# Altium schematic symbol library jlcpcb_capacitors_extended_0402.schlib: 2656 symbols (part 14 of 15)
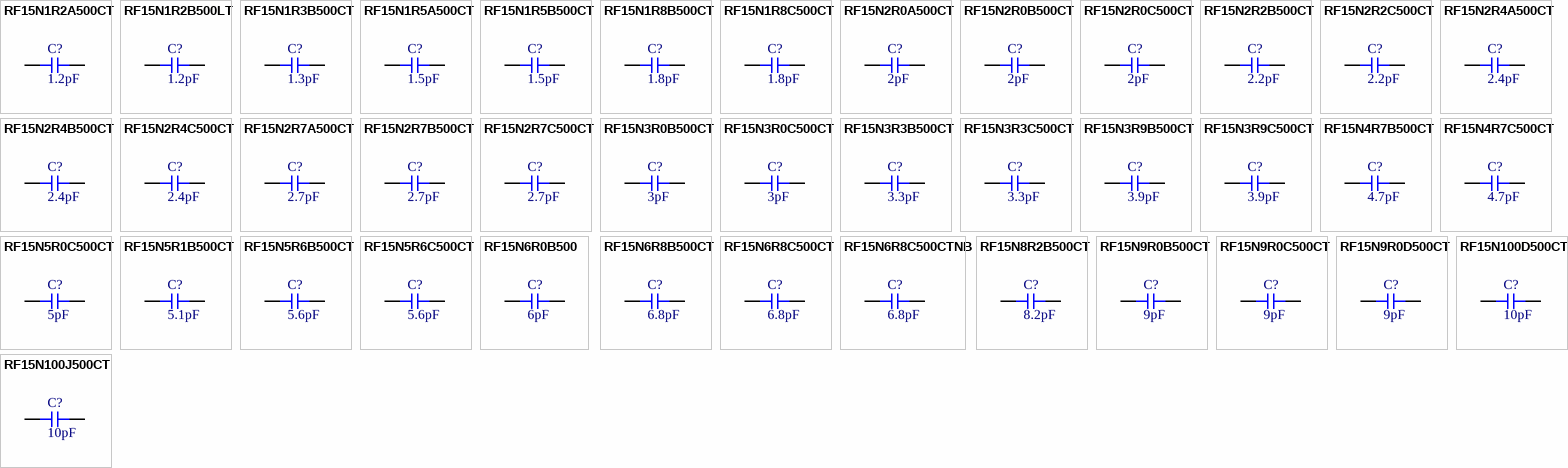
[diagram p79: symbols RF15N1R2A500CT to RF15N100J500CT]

## RF15N2R0B500CT
designator C?  Capacitance: 2pF  (hidden comment: *)
Capacitor, Ceramic (MLCC), 2pF, ±0.1pF, 50V, NP0, ±0.1pF, SMD 0402; Manufacturer: Walsin Tech Corp; Manufacturer Part Number: RF15N2R0B500CT
footprint CAP-0402 (0402 (1005M) Capacitor)
pins: 1, 2

## RF15N2R0C500CT
designator C?  Capacitance: 2pF  (hidden comment: *)
Capacitor, Ceramic (MLCC), 2pF, ±0.25pF, 50V, NP0, ±0.25pF, SMD 0402; Manufacturer: Walsin Tech Corp; Manufacturer Part Number: RF15N2R0C500CT
footprint CAP-0402 (0402 (1005M) Capacitor)
pins: 1, 2

## RF15N2R2B500CT
designator C?  Capacitance: 2.2pF  (hidden comment: *)
Capacitor, Ceramic (MLCC), 2.2pF, ±0.1pF, 50V, NP0, ±0.1pF, SMD 0402; Manufacturer: Walsin Tech Corp; Manufacturer Part Number: RF15N2R2B500CT
footprint CAP-0402 (0402 (1005M) Capacitor)
pins: 1, 2

## RF15N2R2C500CT
designator C?  Capacitance: 2.2pF  (hidden comment: *)
Capacitor, Ceramic (MLCC), 2.2pF, ±0.25pF, 50V, NP0, ±0.25pF, SMD 0402; Manufacturer: Walsin Tech Corp; Manufacturer Part Number: RF15N2R2C500CT
footprint CAP-0402 (0402 (1005M) Capacitor)
pins: 1, 2

## RF15N2R4A500CT
designator C?  Capacitance: 2.4pF  (hidden comment: *)
Capacitor, Ceramic (MLCC), 2.4pF, ±0.05pF, 50V, NP0, ±0.05pF, SMD 0402; Manufacturer: Walsin Tech Corp; Manufacturer Part Number: RF15N2R4A500CT
footprint CAP-0402 (0402 (1005M) Capacitor)
pins: 1, 2

## RF15N2R4B500CT
designator C?  Capacitance: 2.4pF  (hidden comment: *)
Capacitor, Ceramic (MLCC), 2.4pF, ±0.1pF, 50V, NP0, ±0.1pF, SMD 0402; Manufacturer: Walsin Tech Corp; Manufacturer Part Number: RF15N2R4B500CT
footprint CAP-0402 (0402 (1005M) Capacitor)
pins: 1, 2

## RF15N2R4C500CT
designator C?  Capacitance: 2.4pF  (hidden comment: *)
Capacitor, Ceramic (MLCC), 2.4pF, ±0.25pF, 50V, NP0, ±0.25pF, SMD 0402; Manufacturer: Walsin Tech Corp; Manufacturer Part Number: RF15N2R4C500CT
footprint CAP-0402 (0402 (1005M) Capacitor)
pins: 1, 2

## RF15N2R7A500CT
designator C?  Capacitance: 2.7pF  (hidden comment: *)
Capacitor, Ceramic (MLCC), 2.7pF, ±0.05pF, 50V, NP0, ±0.05pF, SMD 0402; Manufacturer: Walsin Tech Corp; Manufacturer Part Number: RF15N2R7A500CT
footprint CAP-0402 (0402 (1005M) Capacitor)
pins: 1, 2

## RF15N2R7B500CT
designator C?  Capacitance: 2.7pF  (hidden comment: *)
Capacitor, Ceramic (MLCC), 2.7pF, ±0.1pF, 50V, NP0, ±0.1pF, SMD 0402; Manufacturer: Walsin Tech Corp; Manufacturer Part Number: RF15N2R7B500CT
footprint CAP-0402 (0402 (1005M) Capacitor)
pins: 1, 2

## RF15N2R7C500CT
designator C?  Capacitance: 2.7pF  (hidden comment: *)
Capacitor, Ceramic (MLCC), 2.7pF, ±0.25pF, 50V, NP0, ±0.25pF, SMD 0402; Manufacturer: Walsin Tech Corp; Manufacturer Part Number: RF15N2R7C500CT
footprint CAP-0402 (0402 (1005M) Capacitor)
pins: 1, 2

## RF15N3R0B500CT
designator C?  Capacitance: 3pF  (hidden comment: *)
Capacitor, Ceramic (MLCC), 3pF, ±0.1pF, 50V, NP0, ±0.1pF, SMD 0402; Manufacturer: Walsin Tech Corp; Manufacturer Part Number: RF15N3R0B500CT
footprint CAP-0402 (0402 (1005M) Capacitor)
pins: 1, 2

## RF15N3R0C500CT
designator C?  Capacitance: 3pF  (hidden comment: *)
Capacitor, Ceramic (MLCC), 3pF, ±0.25pF, 50V, NP0, ±0.25pF, SMD 0402; Manufacturer: Walsin Tech Corp; Manufacturer Part Number: RF15N3R0C500CT
footprint CAP-0402 (0402 (1005M) Capacitor)
pins: 1, 2

## RF15N3R3B500CT
designator C?  Capacitance: 3.3pF  (hidden comment: *)
Capacitor, Ceramic (MLCC), 3.3pF, ±0.1pF, 50V, NP0, ±0.1pF, SMD 0402; Manufacturer: Walsin Tech Corp; Manufacturer Part Number: RF15N3R3B500CT
footprint CAP-0402 (0402 (1005M) Capacitor)
pins: 1, 2

## RF15N3R3C500CT
designator C?  Capacitance: 3.3pF  (hidden comment: *)
Capacitor, Ceramic (MLCC), 3.3pF, ±0.25pF, 50V, NP0, ±0.25pF, SMD 0402; Manufacturer: Walsin Tech Corp; Manufacturer Part Number: RF15N3R3C500CT
footprint CAP-0402 (0402 (1005M) Capacitor)
pins: 1, 2

## RF15N3R9B500CT
designator C?  Capacitance: 3.9pF  (hidden comment: *)
Capacitor, Ceramic (MLCC), 3.9pF, ±0.1pF, 50V, NP0, ±0.1pF, SMD 0402; Manufacturer: Walsin Tech Corp; Manufacturer Part Number: RF15N3R9B500CT
footprint CAP-0402 (0402 (1005M) Capacitor)
pins: 1, 2

## RF15N3R9C500CT
designator C?  Capacitance: 3.9pF  (hidden comment: *)
Capacitor, Ceramic (MLCC), 3.9pF, ±0.25pF, 50V, NP0, ±0.25pF, SMD 0402; Manufacturer: Walsin Tech Corp; Manufacturer Part Number: RF15N3R9C500CT
footprint CAP-0402 (0402 (1005M) Capacitor)
pins: 1, 2

## RF15N4R7B500CT
designator C?  Capacitance: 4.7pF  (hidden comment: *)
Capacitor, Ceramic (MLCC), 4.7pF, ±0.1pF, 50V, NP0, ±0.1pF, SMD 0402; Manufacturer: Walsin Tech Corp; Manufacturer Part Number: RF15N4R7B500CT
footprint CAP-0402 (0402 (1005M) Capacitor)
pins: 1, 2

## RF15N4R7C500CT
designator C?  Capacitance: 4.7pF  (hidden comment: *)
Capacitor, Ceramic (MLCC), 4.7pF, ±0.25pF, 50V, NP0, ±0.25pF, SMD 0402; Manufacturer: Walsin Tech Corp; Manufacturer Part Number: RF15N4R7C500CT
footprint CAP-0402 (0402 (1005M) Capacitor)
pins: 1, 2

## RF15N5R0C500CT
designator C?  Capacitance: 5pF  (hidden comment: *)
Capacitor, Ceramic (MLCC), 5pF, ±0.25pF, 50V, NP0, ±0.25pF, SMD 0402; Manufacturer: Walsin Tech Corp; Manufacturer Part Number: RF15N5R0C500CT
footprint CAP-0402 (0402 (1005M) Capacitor)
pins: 1, 2

## RF15N5R1B500CT
designator C?  Capacitance: 5.1pF  (hidden comment: *)
Capacitor, Ceramic (MLCC), 5.1pF, ±0.1pF, 50V, NP0, ±0.1pF, SMD 0402; Manufacturer: Walsin Tech Corp; Manufacturer Part Number: RF15N5R1B500CT
footprint CAP-0402 (0402 (1005M) Capacitor)
pins: 1, 2

## RF15N5R6B500CT
designator C?  Capacitance: 5.6pF  (hidden comment: *)
Capacitor, Ceramic (MLCC), 5.6pF, ±0.1pF, 50V, NP0, ±0.1pF, SMD 0402; Manufacturer: Walsin Tech Corp; Manufacturer Part Number: RF15N5R6B500CT
footprint CAP-0402 (0402 (1005M) Capacitor)
pins: 1, 2

## RF15N5R6C500CT
designator C?  Capacitance: 5.6pF  (hidden comment: *)
Capacitor, Ceramic (MLCC), 5.6pF, ±0.25pF, 50V, NP0, ±0.25pF, SMD 0402; Manufacturer: Walsin Tech Corp; Manufacturer Part Number: RF15N5R6C500CT
footprint CAP-0402 (0402 (1005M) Capacitor)
pins: 1, 2

## RF15N6R0B500
designator C?  Capacitance: 6pF  (hidden comment: *)
Capacitor, Ceramic (MLCC), 6pF, ±0.1pF, 50V, NP0, ±0.1pF, SMD 0402; Manufacturer: Walsin Tech Corp; Manufacturer Part Number: RF15N6R0B500
footprint CAP-0402 (0402 (1005M) Capacitor)
pins: 1, 2

## RF15N6R8B500CT
designator C?  Capacitance: 6.8pF  (hidden comment: *)
Capacitor, Ceramic (MLCC), 6.8pF, ±0.1pF, 50V, NP0, ±0.1pF, SMD 0402; Manufacturer: Walsin Tech Corp; Manufacturer Part Number: RF15N6R8B500CT
footprint CAP-0402 (0402 (1005M) Capacitor)
pins: 1, 2

## RF15N6R8C500CT
designator C?  Capacitance: 6.8pF  (hidden comment: *)
Capacitor, Ceramic (MLCC), 6.8pF, ±0.25pF, 50V, NP0, ±0.25pF, SMD 0402; Manufacturer: Walsin Tech Corp; Manufacturer Part Number: RF15N6R8C500CT
footprint CAP-0402 (0402 (1005M) Capacitor)
pins: 1, 2

## RF15N6R8C500CTNB
designator C?  Capacitance: 6.8pF  (hidden comment: *)
Capacitor, Ceramic (MLCC), 6.8pF, ±0.25pF, 50V, NP0, ±0.25pF, SMD 0402; Manufacturer: Walsin Tech Corp; Manufacturer Part Number: RF15N6R8C500CTNB
footprint CAP-0402 (0402 (1005M) Capacitor)
pins: 1, 2

## RF15N8R2B500CT
designator C?  Capacitance: 8.2pF  (hidden comment: *)
Capacitor, Ceramic (MLCC), 8.2pF, ±0.1pF, 50V, NP0, ±0.1pF, SMD 0402; Manufacturer: Walsin Tech Corp; Manufacturer Part Number: RF15N8R2B500CT
footprint CAP-0402 (0402 (1005M) Capacitor)
pins: 1, 2

## RF15N9R0B500CT
designator C?  Capacitance: 9pF  (hidden comment: *)
Capacitor, Ceramic (MLCC), 9pF, ±0.1pF, 50V, NP0, ±0.1pF, SMD 0402; Manufacturer: Walsin Tech Corp; Manufacturer Part Number: RF15N9R0B500CT
footprint CAP-0402 (0402 (1005M) Capacitor)
pins: 1, 2

## RF15N9R0C500CT
designator C?  Capacitance: 9pF  (hidden comment: *)
Capacitor, Ceramic (MLCC), 9pF, ±0.25pF, 50V, NP0, ±0.25pF, SMD 0402; Manufacturer: Walsin Tech Corp; Manufacturer Part Number: RF15N9R0C500CT
footprint CAP-0402 (0402 (1005M) Capacitor)
pins: 1, 2

## RF15N9R0D500CT
designator C?  Capacitance: 9pF  (hidden comment: *)
Capacitor, Ceramic (MLCC), 9pF, ±0.5pF, 50V, NP0, ±0.5pF, SMD 0402; Manufacturer: Walsin Tech Corp; Manufacturer Part Number: RF15N9R0D500CT
footprint CAP-0402 (0402 (1005M) Capacitor)
pins: 1, 2

## RF15N100D500CT
designator C?  Capacitance: 10pF  (hidden comment: *)
Capacitor, Ceramic (MLCC), 10pF, ±0.5pF, 50V, NP0, ±0.5pF, SMD 0402; Manufacturer: Walsin Tech Corp; Manufacturer Part Number: RF15N100D500CT
footprint CAP-0402 (0402 (1005M) Capacitor)
pins: 1, 2

## RF15N100J500CT
designator C?  Capacitance: 10pF  (hidden comment: *)
Capacitor, Ceramic (MLCC), 10pF, ±5%, 50V, NP0, ±5%, SMD 0402; Manufacturer: Walsin Tech Corp; Manufacturer Part Number: RF15N100J500CT
footprint CAP-0402 (0402 (1005M) Capacitor)
pins: 1, 2

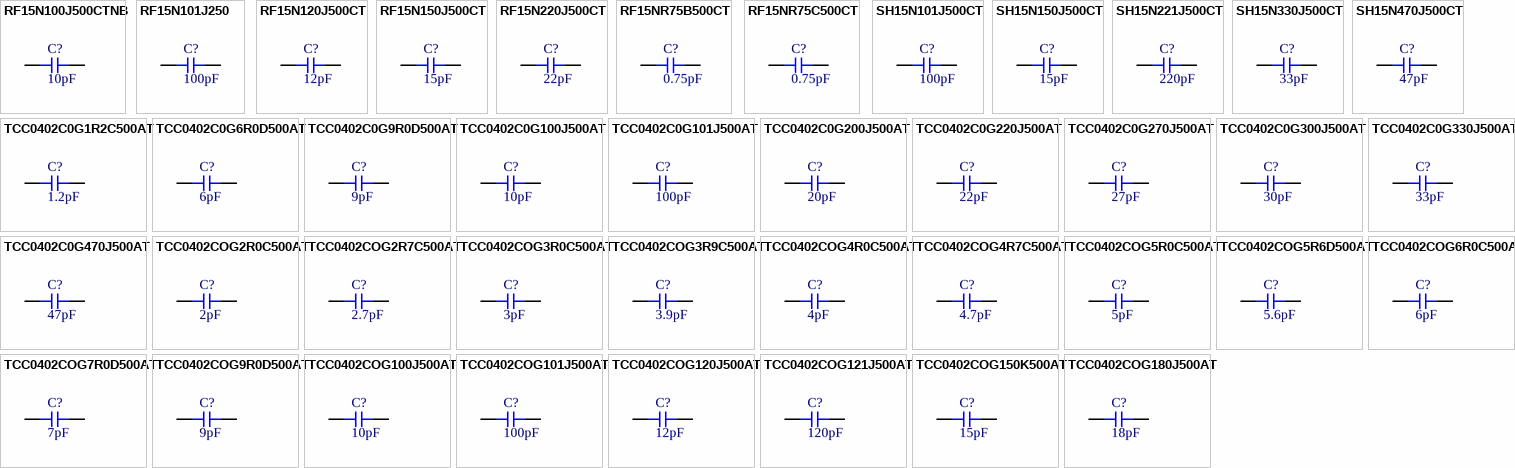
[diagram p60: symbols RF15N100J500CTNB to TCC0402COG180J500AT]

## RF15N100J500CTNB
designator C?  Capacitance: 10pF  (hidden comment: *)
Capacitor, Ceramic (MLCC), 10pF, ±5%, 50V, NP0, ±5%, SMD 0402; Manufacturer: Walsin Tech Corp; Manufacturer Part Number: RF15N100J500CTNB
footprint CAP-0402 (0402 (1005M) Capacitor)
pins: 1, 2

## RF15N101J250
designator C?  Capacitance: 100pF  (hidden comment: *)
Capacitor, Ceramic (MLCC), 100pF, ±5%, 25V, NP0, ±5%, SMD 0402; Manufacturer: Walsin Tech Corp; Manufacturer Part Number: RF15N101J250
footprint CAP-0402 (0402 (1005M) Capacitor)
pins: 1, 2

## RF15N120J500CT
designator C?  Capacitance: 12pF  (hidden comment: *)
Capacitor, Ceramic (MLCC), 12pF, ±5%, 50V, NP0, ±5%, SMD 0402; Manufacturer: Walsin Tech Corp; Manufacturer Part Number: RF15N120J500CT
footprint CAP-0402 (0402 (1005M) Capacitor)
pins: 1, 2

## RF15N150J500CT
designator C?  Capacitance: 15pF  (hidden comment: *)
Capacitor, Ceramic (MLCC), 15pF, ±5%, 50V, NP0, ±5%, SMD 0402; Manufacturer: Walsin Tech Corp; Manufacturer Part Number: RF15N150J500CT
footprint CAP-0402 (0402 (1005M) Capacitor)
pins: 1, 2

## RF15N220J500CT
designator C?  Capacitance: 22pF  (hidden comment: *)
Capacitor, Ceramic (MLCC), 22pF, ±5%, 50V, NP0, ±5%, SMD 0402; Manufacturer: Walsin Tech Corp; Manufacturer Part Number: RF15N220J500CT
footprint CAP-0402 (0402 (1005M) Capacitor)
pins: 1, 2

## RF15NR75B500CT
designator C?  Capacitance: 0.75pF  (hidden comment: *)
Capacitor, Ceramic (MLCC), 0.75pF, ±0.1pF, 50V, NP0, ±0.1pF, SMD 0402; Manufacturer: Walsin Tech Corp; Manufacturer Part Number: RF15NR75B500CT
footprint CAP-0402 (0402 (1005M) Capacitor)
pins: 1, 2

## RF15NR75C500CT
designator C?  Capacitance: 0.75pF  (hidden comment: *)
Capacitor, Ceramic (MLCC), 0.75pF, ±0.25pF, 50V, NP0, ±0.25pF, SMD 0402; Manufacturer: Walsin Tech Corp; Manufacturer Part Number: RF15NR75C500CT
footprint CAP-0402 (0402 (1005M) Capacitor)
pins: 1, 2

## SH15N101J500CT
designator C?  Capacitance: 100pF  (hidden comment: *)
Capacitor, Ceramic (MLCC), 100pF, ±5%, 50V, NP0, ±5%, SMD 0402; Manufacturer: Walsin Tech Corp; Manufacturer Part Number: SH15N101J500CT
footprint CAP-0402 (0402 (1005M) Capacitor)
pins: 1, 2

## SH15N150J500CT
designator C?  Capacitance: 15pF  (hidden comment: *)
Capacitor, Ceramic (MLCC), 15pF, ±5%, 50V, NP0, ±5%, SMD 0402; Manufacturer: Walsin Tech Corp; Manufacturer Part Number: SH15N150J500CT
footprint CAP-0402 (0402 (1005M) Capacitor)
pins: 1, 2

## SH15N221J500CT
designator C?  Capacitance: 220pF  (hidden comment: *)
Capacitor, Ceramic (MLCC), 220pF, ±5%, 50V, NP0, ±5%, SMD 0402; Manufacturer: Walsin Tech Corp; Manufacturer Part Number: SH15N221J500CT
footprint CAP-0402 (0402 (1005M) Capacitor)
pins: 1, 2

## SH15N330J500CT
designator C?  Capacitance: 33pF  (hidden comment: *)
Capacitor, Ceramic (MLCC), 33pF, ±5%, 50V, NP0, ±5%, SMD 0402; Manufacturer: Walsin Tech Corp; Manufacturer Part Number: SH15N330J500CT
footprint CAP-0402 (0402 (1005M) Capacitor)
pins: 1, 2

## SH15N470J500CT
designator C?  Capacitance: 47pF  (hidden comment: *)
Capacitor, Ceramic (MLCC), 47pF, ±5%, 50V, NP0, ±5%, SMD 0402; Manufacturer: Walsin Tech Corp; Manufacturer Part Number: SH15N470J500CT
footprint CAP-0402 (0402 (1005M) Capacitor)
pins: 1, 2

## TCC0402C0G1R2C500AT
designator C?  Capacitance: 1.2pF  (hidden comment: *)
Capacitor, Ceramic (MLCC), 1.2pF, ±0.25pF, 50V, C0G, ±0.25pF, SMD 0402; Manufacturer: CCTC; Manufacturer Part Number: TCC0402C0G1R2C500AT
footprint CAP-0402 (0402 (1005M) Capacitor)
pins: 1, 2

## TCC0402C0G6R0D500AT
designator C?  Capacitance: 6pF  (hidden comment: *)
Capacitor, Ceramic (MLCC), 6pF, ±0.5pF, 50V, C0G, ±0.5pF, SMD 0402; Manufacturer: CCTC; Manufacturer Part Number: TCC0402C0G6R0D500AT
footprint CAP-0402 (0402 (1005M) Capacitor)
pins: 1, 2

## TCC0402C0G9R0D500AT
designator C?  Capacitance: 9pF  (hidden comment: *)
Capacitor, Ceramic (MLCC), 9pF, ±0.5pF, 50V, C0G, ±0.5pF, SMD 0402; Manufacturer: CCTC; Manufacturer Part Number: TCC0402C0G9R0D500AT
footprint CAP-0402 (0402 (1005M) Capacitor)
pins: 1, 2

## TCC0402C0G100J500AT
designator C?  Capacitance: 10pF  (hidden comment: *)
Capacitor, Ceramic (MLCC), 10pF, ±5%, 50V, C0G, ±5%, SMD 0402; Manufacturer: CCTC; Manufacturer Part Number: TCC0402C0G100J500AT
footprint CAP-0402 (0402 (1005M) Capacitor)
pins: 1, 2

## TCC0402C0G101J500AT
designator C?  Capacitance: 100pF  (hidden comment: *)
Capacitor, Ceramic (MLCC), 100pF, ±5%, 50V, C0G, ±5%, SMD 0402; Manufacturer: CCTC; Manufacturer Part Number: TCC0402C0G101J500AT
footprint CAP-0402 (0402 (1005M) Capacitor)
pins: 1, 2

## TCC0402C0G200J500AT
designator C?  Capacitance: 20pF  (hidden comment: *)
Capacitor, Ceramic (MLCC), 20pF, ±5%, 50V, C0G, ±5%, SMD 0402; Manufacturer: CCTC; Manufacturer Part Number: TCC0402C0G200J500AT
footprint CAP-0402 (0402 (1005M) Capacitor)
pins: 1, 2

## TCC0402C0G220J500AT
designator C?  Capacitance: 22pF  (hidden comment: *)
Capacitor, Ceramic (MLCC), 22pF, ±5%, 50V, C0G, ±5%, SMD 0402; Manufacturer: CCTC; Manufacturer Part Number: TCC0402C0G220J500AT
footprint CAP-0402 (0402 (1005M) Capacitor)
pins: 1, 2

## TCC0402C0G270J500AT
designator C?  Capacitance: 27pF  (hidden comment: *)
Capacitor, Ceramic (MLCC), 27pF, ±5%, 50V, C0G, ±5%, SMD 0402; Manufacturer: CCTC; Manufacturer Part Number: TCC0402C0G270J500AT
footprint CAP-0402 (0402 (1005M) Capacitor)
pins: 1, 2

## TCC0402C0G300J500AT
designator C?  Capacitance: 30pF  (hidden comment: *)
Capacitor, Ceramic (MLCC), 30pF, ±5%, 50V, C0G, ±5%, SMD 0402; Manufacturer: CCTC; Manufacturer Part Number: TCC0402C0G300J500AT
footprint CAP-0402 (0402 (1005M) Capacitor)
pins: 1, 2

## TCC0402C0G330J500AT
designator C?  Capacitance: 33pF  (hidden comment: *)
Capacitor, Ceramic (MLCC), 33pF, ±5%, 50V, C0G, ±5%, SMD 0402; Manufacturer: CCTC; Manufacturer Part Number: TCC0402C0G330J500AT
footprint CAP-0402 (0402 (1005M) Capacitor)
pins: 1, 2

## TCC0402C0G470J500AT
designator C?  Capacitance: 47pF  (hidden comment: *)
Capacitor, Ceramic (MLCC), 47pF, ±5%, 50V, C0G, ±5%, SMD 0402; Manufacturer: CCTC; Manufacturer Part Number: TCC0402C0G470J500AT
footprint CAP-0402 (0402 (1005M) Capacitor)
pins: 1, 2

## TCC0402COG2R0C500AT
designator C?  Capacitance: 2pF  (hidden comment: *)
Capacitor, Ceramic (MLCC), 2pF, ±0.25pF, 50V, C0G, ±0.25pF, SMD 0402; Manufacturer: CCTC; Manufacturer Part Number: TCC0402COG2R0C500AT
footprint CAP-0402 (0402 (1005M) Capacitor)
pins: 1, 2

## TCC0402COG2R7C500AT
designator C?  Capacitance: 2.7pF  (hidden comment: *)
Capacitor, Ceramic (MLCC), 2.7pF, ±0.25pF, 50V, C0G, ±0.25pF, SMD 0402; Manufacturer: CCTC; Manufacturer Part Number: TCC0402COG2R7C500AT
footprint CAP-0402 (0402 (1005M) Capacitor)
pins: 1, 2

## TCC0402COG3R0C500AT
designator C?  Capacitance: 3pF  (hidden comment: *)
Capacitor, Ceramic (MLCC), 3pF, ±0.25pF, 50V, C0G, ±0.25pF, SMD 0402; Manufacturer: CCTC; Manufacturer Part Number: TCC0402COG3R0C500AT
footprint CAP-0402 (0402 (1005M) Capacitor)
pins: 1, 2

## TCC0402COG3R9C500AT
designator C?  Capacitance: 3.9pF  (hidden comment: *)
Capacitor, Ceramic (MLCC), 3.9pF, ±0.25pF, 50V, C0G, ±0.25pF, SMD 0402; Manufacturer: CCTC; Manufacturer Part Number: TCC0402COG3R9C500AT
footprint CAP-0402 (0402 (1005M) Capacitor)
pins: 1, 2

## TCC0402COG4R0C500AT
designator C?  Capacitance: 4pF  (hidden comment: *)
Capacitor, Ceramic (MLCC), 4pF, ±0.25pF, 50V, C0G, ±0.25pF, SMD 0402; Manufacturer: CCTC; Manufacturer Part Number: TCC0402COG4R0C500AT
footprint CAP-0402 (0402 (1005M) Capacitor)
pins: 1, 2

## TCC0402COG4R7C500AT
designator C?  Capacitance: 4.7pF  (hidden comment: *)
Capacitor, Ceramic (MLCC), 4.7pF, ±0.25pF, 50V, C0G, ±0.25pF, SMD 0402; Manufacturer: CCTC; Manufacturer Part Number: TCC0402COG4R7C500AT
footprint CAP-0402 (0402 (1005M) Capacitor)
pins: 1, 2

## TCC0402COG5R0C500AT
designator C?  Capacitance: 5pF  (hidden comment: *)
Capacitor, Ceramic (MLCC), 5pF, ±0.25pF, 50V, C0G, ±0.25pF, SMD 0402; Manufacturer: CCTC; Manufacturer Part Number: TCC0402COG5R0C500AT
footprint CAP-0402 (0402 (1005M) Capacitor)
pins: 1, 2

## TCC0402COG5R6D500AT
designator C?  Capacitance: 5.6pF  (hidden comment: *)
Capacitor, Ceramic (MLCC), 5.6pF, ±0.5pF, 50V, C0G, ±0.5pF, SMD 0402; Manufacturer: CCTC; Manufacturer Part Number: TCC0402COG5R6D500AT
footprint CAP-0402 (0402 (1005M) Capacitor)
pins: 1, 2

## TCC0402COG6R0C500AT
designator C?  Capacitance: 6pF  (hidden comment: *)
Capacitor, Ceramic (MLCC), 6pF, ±0.25pF, 50V, C0G, ±0.25pF, SMD 0402; Manufacturer: CCTC; Manufacturer Part Number: TCC0402COG6R0C500AT
footprint CAP-0402 (0402 (1005M) Capacitor)
pins: 1, 2

## TCC0402COG7R0D500AT
designator C?  Capacitance: 7pF  (hidden comment: *)
Capacitor, Ceramic (MLCC), 7pF, ±0.5pF, 50V, C0G, ±0.5pF, SMD 0402; Manufacturer: CCTC; Manufacturer Part Number: TCC0402COG7R0D500AT
footprint CAP-0402 (0402 (1005M) Capacitor)
pins: 1, 2

## TCC0402COG9R0D500AT
designator C?  Capacitance: 9pF  (hidden comment: *)
Capacitor, Ceramic (MLCC), 9pF, ±0.5pF, 50V, C0G, ±0.5pF, SMD 0402; Manufacturer: CCTC; Manufacturer Part Number: TCC0402COG9R0D500AT
footprint CAP-0402 (0402 (1005M) Capacitor)
pins: 1, 2

## TCC0402COG100J500AT
designator C?  Capacitance: 10pF  (hidden comment: *)
Capacitor, Ceramic (MLCC), 10pF, ±5%, 50V, C0G, ±5%, SMD 0402; Manufacturer: CCTC; Manufacturer Part Number: TCC0402COG100J500AT
footprint CAP-0402 (0402 (1005M) Capacitor)
pins: 1, 2

## TCC0402COG101J500AT
designator C?  Capacitance: 100pF  (hidden comment: *)
Capacitor, Ceramic (MLCC), 100pF, ±5%, 50V, C0G, ±5%, SMD 0402; Manufacturer: CCTC; Manufacturer Part Number: TCC0402COG101J500AT
footprint CAP-0402 (0402 (1005M) Capacitor)
pins: 1, 2

## TCC0402COG120J500AT
designator C?  Capacitance: 12pF  (hidden comment: *)
Capacitor, Ceramic (MLCC), 12pF, ±5%, 50V, C0G, ±5%, SMD 0402; Manufacturer: CCTC; Manufacturer Part Number: TCC0402COG120J500AT
footprint CAP-0402 (0402 (1005M) Capacitor)
pins: 1, 2

## TCC0402COG121J500AT
designator C?  Capacitance: 120pF  (hidden comment: *)
Capacitor, Ceramic (MLCC), 120pF, ±5%, 50V, ±5%, SMD 0402; Manufacturer: CCTC; Manufacturer Part Number: TCC0402COG121J500AT
footprint CAP-0402 (0402 (1005M) Capacitor)
pins: 1, 2

## TCC0402COG150K500AT
designator C?  Capacitance: 15pF  (hidden comment: *)
Capacitor, Ceramic (MLCC), 15pF, ±10%, 50V, C0G, ±10%, SMD 0402; Manufacturer: CCTC; Manufacturer Part Number: TCC0402COG150K500AT
footprint CAP-0402 (0402 (1005M) Capacitor)
pins: 1, 2

## TCC0402COG180J500AT
designator C?  Capacitance: 18pF  (hidden comment: *)
Capacitor, Ceramic (MLCC), 18pF, ±5%, 50V, C0G, ±5%, SMD 0402; Manufacturer: CCTC; Manufacturer Part Number: TCC0402COG180J500AT
footprint CAP-0402 (0402 (1005M) Capacitor)
pins: 1, 2

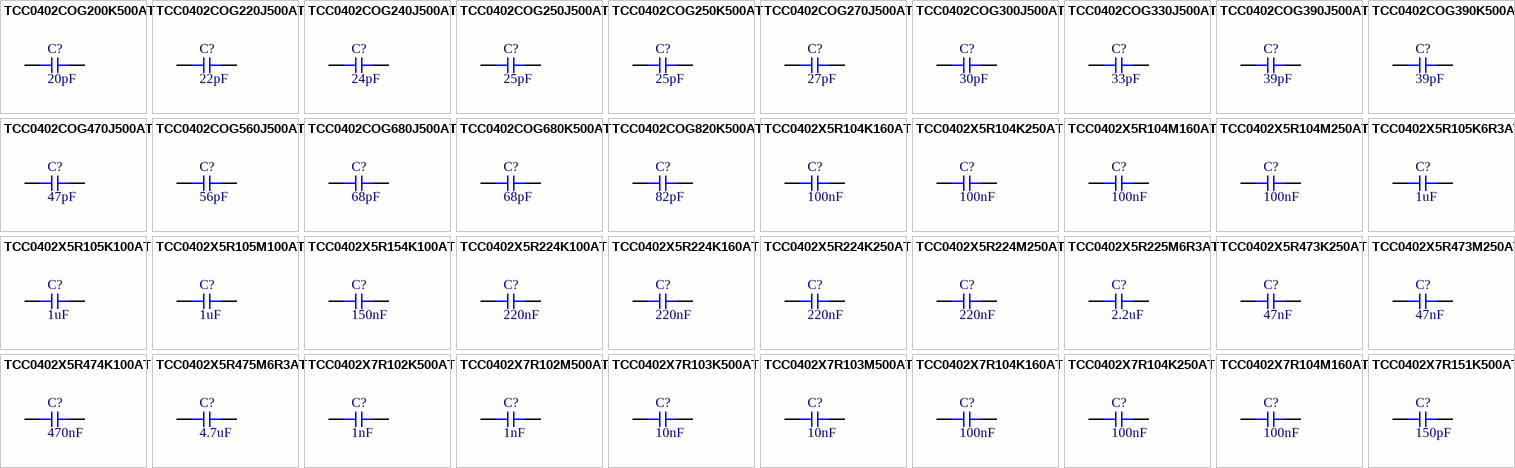
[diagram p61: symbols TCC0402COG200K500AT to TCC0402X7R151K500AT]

## TCC0402COG200K500AT
designator C?  Capacitance: 20pF  (hidden comment: *)
Capacitor, Ceramic (MLCC), 20pF, ±10%, 50V, C0G, ±10%, SMD 0402; Manufacturer: CCTC; Manufacturer Part Number: TCC0402COG200K500AT
footprint CAP-0402 (0402 (1005M) Capacitor)
pins: 1, 2

## TCC0402COG220J500AT
designator C?  Capacitance: 22pF  (hidden comment: *)
Capacitor, Ceramic (MLCC), 22pF, ±5%, 50V, C0G, ±5%, SMD 0402; Manufacturer: CCTC; Manufacturer Part Number: TCC0402COG220J500AT
footprint CAP-0402 (0402 (1005M) Capacitor)
pins: 1, 2

## TCC0402COG240J500AT
designator C?  Capacitance: 24pF  (hidden comment: *)
Capacitor, Ceramic (MLCC), 24pF, ±5%, 50V, C0G, ±5%, SMD 0402; Manufacturer: CCTC; Manufacturer Part Number: TCC0402COG240J500AT
footprint CAP-0402 (0402 (1005M) Capacitor)
pins: 1, 2

## TCC0402COG250J500AT
designator C?  Capacitance: 25pF  (hidden comment: *)
Capacitor, Ceramic (MLCC), 25pF, ±5%, 50V, C0G, ±5%, SMD 0402; Manufacturer: CCTC; Manufacturer Part Number: TCC0402COG250J500AT
footprint CAP-0402 (0402 (1005M) Capacitor)
pins: 1, 2

## TCC0402COG250K500AT
designator C?  Capacitance: 25pF  (hidden comment: *)
Capacitor, Ceramic (MLCC), 25pF, ±10%, 50V, C0G, ±10%, SMD 0402; Manufacturer: CCTC; Manufacturer Part Number: TCC0402COG250K500AT
footprint CAP-0402 (0402 (1005M) Capacitor)
pins: 1, 2

## TCC0402COG270J500AT
designator C?  Capacitance: 27pF  (hidden comment: *)
Capacitor, Ceramic (MLCC), 27pF, ±5%, 50V, C0G, ±5%, SMD 0402; Manufacturer: CCTC; Manufacturer Part Number: TCC0402COG270J500AT
footprint CAP-0402 (0402 (1005M) Capacitor)
pins: 1, 2

## TCC0402COG300J500AT
designator C?  Capacitance: 30pF  (hidden comment: *)
Capacitor, Ceramic (MLCC), 30pF, ±5%, 50V, C0G, ±5%, SMD 0402; Manufacturer: CCTC; Manufacturer Part Number: TCC0402COG300J500AT
footprint CAP-0402 (0402 (1005M) Capacitor)
pins: 1, 2

## TCC0402COG330J500AT
designator C?  Capacitance: 33pF  (hidden comment: *)
Capacitor, Ceramic (MLCC), 33pF, ±5%, 50V, C0G, ±5%, SMD 0402; Manufacturer: CCTC; Manufacturer Part Number: TCC0402COG330J500AT
footprint CAP-0402 (0402 (1005M) Capacitor)
pins: 1, 2

## TCC0402COG390J500AT
designator C?  Capacitance: 39pF  (hidden comment: *)
Capacitor, Ceramic (MLCC), 39pF, ±5%, 50V, C0G, ±5%, SMD 0402; Manufacturer: CCTC; Manufacturer Part Number: TCC0402COG390J500AT
footprint CAP-0402 (0402 (1005M) Capacitor)
pins: 1, 2

## TCC0402COG390K500AT
designator C?  Capacitance: 39pF  (hidden comment: *)
Capacitor, Ceramic (MLCC), 39pF, ±10%, 50V, C0G, ±10%, SMD 0402; Manufacturer: CCTC; Manufacturer Part Number: TCC0402COG390K500AT
footprint CAP-0402 (0402 (1005M) Capacitor)
pins: 1, 2

## TCC0402COG470J500AT
designator C?  Capacitance: 47pF  (hidden comment: *)
Capacitor, Ceramic (MLCC), 47pF, ±5%, 50V, C0G, ±5%, SMD 0402; Manufacturer: CCTC; Manufacturer Part Number: TCC0402COG470J500AT
footprint CAP-0402 (0402 (1005M) Capacitor)
pins: 1, 2

## TCC0402COG560J500AT
designator C?  Capacitance: 56pF  (hidden comment: *)
Capacitor, Ceramic (MLCC), 56pF, ±5%, 50V, C0G, ±5%, SMD 0402; Manufacturer: CCTC; Manufacturer Part Number: TCC0402COG560J500AT
footprint CAP-0402 (0402 (1005M) Capacitor)
pins: 1, 2

## TCC0402COG680J500AT
designator C?  Capacitance: 68pF  (hidden comment: *)
Capacitor, Ceramic (MLCC), 68pF, ±5%, 50V, C0G, ±5%, SMD 0402; Manufacturer: CCTC; Manufacturer Part Number: TCC0402COG680J500AT
footprint CAP-0402 (0402 (1005M) Capacitor)
pins: 1, 2

## TCC0402COG680K500AT
designator C?  Capacitance: 68pF  (hidden comment: *)
Capacitor, Ceramic (MLCC), 68pF, ±10%, 50V, C0G, ±10%, SMD 0402; Manufacturer: CCTC; Manufacturer Part Number: TCC0402COG680K500AT
footprint CAP-0402 (0402 (1005M) Capacitor)
pins: 1, 2

## TCC0402COG820K500AT
designator C?  Capacitance: 82pF  (hidden comment: *)
Capacitor, Ceramic (MLCC), 82pF, ±10%, 50V, C0G, ±10%, SMD 0402; Manufacturer: CCTC; Manufacturer Part Number: TCC0402COG820K500AT
footprint CAP-0402 (0402 (1005M) Capacitor)
pins: 1, 2

## TCC0402X5R104K160AT
designator C?  Capacitance: 100nF  (hidden comment: *)
Capacitor, Ceramic (MLCC), 100nF, ±10%, 16V, X5R, ±10%, SMD 0402; Manufacturer: CCTC; Manufacturer Part Number: TCC0402X5R104K160AT
footprint CAP-0402 (0402 (1005M) Capacitor)
pins: 1, 2

## TCC0402X5R104K250AT
designator C?  Capacitance: 100nF  (hidden comment: *)
Capacitor, Ceramic (MLCC), 100nF, ±10%, 25V, X5R, ±10%, SMD 0402; Manufacturer: CCTC; Manufacturer Part Number: TCC0402X5R104K250AT
footprint CAP-0402 (0402 (1005M) Capacitor)
pins: 1, 2

## TCC0402X5R104M160AT
designator C?  Capacitance: 100nF  (hidden comment: *)
Capacitor, Ceramic (MLCC), 100nF, ±20%, 16V, X5R, ±20%, SMD 0402; Manufacturer: CCTC; Manufacturer Part Number: TCC0402X5R104M160AT
footprint CAP-0402 (0402 (1005M) Capacitor)
pins: 1, 2

## TCC0402X5R104M250AT
designator C?  Capacitance: 100nF  (hidden comment: *)
Capacitor, Ceramic (MLCC), 100nF, ±20%, 25V, X5R, ±20%, SMD 0402; Manufacturer: CCTC; Manufacturer Part Number: TCC0402X5R104M250AT
footprint CAP-0402 (0402 (1005M) Capacitor)
pins: 1, 2

## TCC0402X5R105K6R3AT
designator C?  Capacitance: 1uF  (hidden comment: *)
Capacitor, Ceramic (MLCC), 1uF, ±10%, 6.3V, X5R, ±10%, SMD 0402; Manufacturer: CCTC; Manufacturer Part Number: TCC0402X5R105K6R3AT
footprint CAP-0402 (0402 (1005M) Capacitor)
pins: 1, 2

## TCC0402X5R105K100AT
designator C?  Capacitance: 1uF  (hidden comment: *)
Capacitor, Ceramic (MLCC), 1uF, ±10%, 10V, X5R, ±10%, SMD 0402; Manufacturer: CCTC; Manufacturer Part Number: TCC0402X5R105K100AT
footprint CAP-0402 (0402 (1005M) Capacitor)
pins: 1, 2

## TCC0402X5R105M100AT
designator C?  Capacitance: 1uF  (hidden comment: *)
Capacitor, Ceramic (MLCC), 1uF, ±20%, 10V, Y5V, ±20%, SMD 0402; Manufacturer: CCTC; Manufacturer Part Number: TCC0402X5R105M100AT
footprint CAP-0402 (0402 (1005M) Capacitor)
pins: 1, 2

## TCC0402X5R154K100AT
designator C?  Capacitance: 150nF  (hidden comment: *)
Capacitor, Ceramic (MLCC), 150nF, ±10%, 10V, X5R, ±10%, SMD 0402; Manufacturer: CCTC; Manufacturer Part Number: TCC0402X5R154K100AT
footprint CAP-0402 (0402 (1005M) Capacitor)
pins: 1, 2

## TCC0402X5R224K100AT
designator C?  Capacitance: 220nF  (hidden comment: *)
Capacitor, Ceramic (MLCC), 220nF, ±10%, 10V, X5R, ±10%, SMD 0402; Manufacturer: CCTC; Manufacturer Part Number: TCC0402X5R224K100AT
footprint CAP-0402 (0402 (1005M) Capacitor)
pins: 1, 2

## TCC0402X5R224K160AT
designator C?  Capacitance: 220nF  (hidden comment: *)
Capacitor, Ceramic (MLCC), 220nF, ±10%, 16V, X5R, ±10%, SMD 0402; Manufacturer: CCTC; Manufacturer Part Number: TCC0402X5R224K160AT
footprint CAP-0402 (0402 (1005M) Capacitor)
pins: 1, 2

## TCC0402X5R224K250AT
designator C?  Capacitance: 220nF  (hidden comment: *)
Capacitor, Ceramic (MLCC), 220nF, ±10%, 25V, X5R, ±10%, SMD 0402; Manufacturer: CCTC; Manufacturer Part Number: TCC0402X5R224K250AT
footprint CAP-0402 (0402 (1005M) Capacitor)
pins: 1, 2

## TCC0402X5R224M250AT
designator C?  Capacitance: 220nF  (hidden comment: *)
Capacitor, Ceramic (MLCC), 220nF, ±20%, 25V, X5R, ±20%, SMD 0402; Manufacturer: CCTC; Manufacturer Part Number: TCC0402X5R224M250AT
footprint CAP-0402 (0402 (1005M) Capacitor)
pins: 1, 2

## TCC0402X5R225M6R3AT
designator C?  Capacitance: 2.2uF  (hidden comment: *)
Capacitor, Ceramic (MLCC), 2.2uF, ±20%, 6.3V, X5R, ±20%, SMD 0402; Manufacturer: CCTC; Manufacturer Part Number: TCC0402X5R225M6R3AT
footprint CAP-0402 (0402 (1005M) Capacitor)
pins: 1, 2

## TCC0402X5R473K250AT
designator C?  Capacitance: 47nF  (hidden comment: *)
Capacitor, Ceramic (MLCC), 47nF, ±10%, 25V, X5R, ±10%, SMD 0402; Manufacturer: CCTC; Manufacturer Part Number: TCC0402X5R473K250AT
footprint CAP-0402 (0402 (1005M) Capacitor)
pins: 1, 2

## TCC0402X5R473M250AT
designator C?  Capacitance: 47nF  (hidden comment: *)
Capacitor, Ceramic (MLCC), 47nF, ±20%, 25V, X5R, ±20%, SMD 0402; Manufacturer: CCTC; Manufacturer Part Number: TCC0402X5R473M250AT
footprint CAP-0402 (0402 (1005M) Capacitor)
pins: 1, 2

## TCC0402X5R474K100AT
designator C?  Capacitance: 470nF  (hidden comment: *)
Capacitor, Ceramic (MLCC), 470nF, ±10%, 10V, X5R, ±10%, SMD 0402; Manufacturer: CCTC; Manufacturer Part Number: TCC0402X5R474K100AT
footprint CAP-0402 (0402 (1005M) Capacitor)
pins: 1, 2

## TCC0402X5R475M6R3AT
designator C?  Capacitance: 4.7uF  (hidden comment: *)
Capacitor, Ceramic (MLCC), 4.7uF, ±20%, 6.3V, X5R, ±20%, SMD 0402; Manufacturer: CCTC; Manufacturer Part Number: TCC0402X5R475M6R3AT
footprint CAP-0402 (0402 (1005M) Capacitor)
pins: 1, 2

## TCC0402X7R102K500AT
designator C?  Capacitance: 1nF  (hidden comment: *)
Capacitor, Ceramic (MLCC), 1nF, ±10%, 50V, X7R, ±10%, SMD 0402; Manufacturer: CCTC; Manufacturer Part Number: TCC0402X7R102K500AT
footprint CAP-0402 (0402 (1005M) Capacitor)
pins: 1, 2

## TCC0402X7R102M500AT
designator C?  Capacitance: 1nF  (hidden comment: *)
Capacitor, Ceramic (MLCC), 1nF, ±20%, 50V, X7R, ±20%, SMD 0402; Manufacturer: CCTC; Manufacturer Part Number: TCC0402X7R102M500AT
footprint CAP-0402 (0402 (1005M) Capacitor)
pins: 1, 2

## TCC0402X7R103K500AT
designator C?  Capacitance: 10nF  (hidden comment: *)
Capacitor, Ceramic (MLCC), 10nF, ±10%, 50V, X7R, ±10%, SMD 0402; Manufacturer: CCTC; Manufacturer Part Number: TCC0402X7R103K500AT
footprint CAP-0402 (0402 (1005M) Capacitor)
pins: 1, 2

## TCC0402X7R103M500AT
designator C?  Capacitance: 10nF  (hidden comment: *)
Capacitor, Ceramic (MLCC), 10nF, ±20%, 50V, X7R, ±20%, SMD 0402; Manufacturer: CCTC; Manufacturer Part Number: TCC0402X7R103M500AT
footprint CAP-0402 (0402 (1005M) Capacitor)
pins: 1, 2

## TCC0402X7R104K160AT
designator C?  Capacitance: 100nF  (hidden comment: *)
Capacitor, Ceramic (MLCC), 100nF, ±10%, 16V, X7R, ±10%, SMD 0402; Manufacturer: CCTC; Manufacturer Part Number: TCC0402X7R104K160AT
footprint CAP-0402 (0402 (1005M) Capacitor)
pins: 1, 2

## TCC0402X7R104K250AT
designator C?  Capacitance: 100nF  (hidden comment: *)
Capacitor, Ceramic (MLCC), 100nF, ±10%, 25V, X7R, ±10%, SMD 0402; Manufacturer: CCTC; Manufacturer Part Number: TCC0402X7R104K250AT
footprint CAP-0402 (0402 (1005M) Capacitor)
pins: 1, 2

## TCC0402X7R104M160AT
designator C?  Capacitance: 100nF  (hidden comment: *)
Capacitor, Ceramic (MLCC), 100nF, ±20%, 16V, X7R, ±20%, SMD 0402; Manufacturer: CCTC; Manufacturer Part Number: TCC0402X7R104M160AT
footprint CAP-0402 (0402 (1005M) Capacitor)
pins: 1, 2

## TCC0402X7R151K500AT
designator C?  Capacitance: 150pF  (hidden comment: *)
Capacitor, Ceramic (MLCC), 150pF, ±10%, 50V, X7R, ±10%, SMD 0402; Manufacturer: CCTC; Manufacturer Part Number: TCC0402X7R151K500AT
footprint CAP-0402 (0402 (1005M) Capacitor)
pins: 1, 2

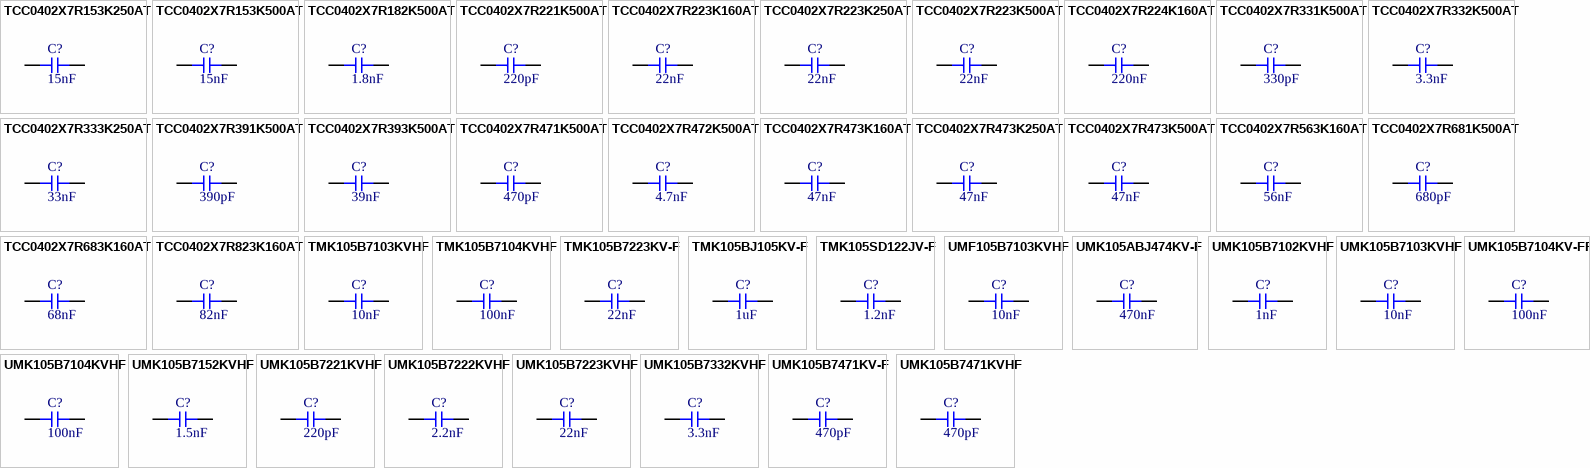
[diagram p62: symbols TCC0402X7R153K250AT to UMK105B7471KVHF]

## TCC0402X7R153K250AT
designator C?  Capacitance: 15nF  (hidden comment: *)
Capacitor, Ceramic (MLCC), 15nF, ±10%, 25V, X7R, ±10%, SMD 0402; Manufacturer: CCTC; Manufacturer Part Number: TCC0402X7R153K250AT
footprint CAP-0402 (0402 (1005M) Capacitor)
pins: 1, 2

## TCC0402X7R153K500AT
designator C?  Capacitance: 15nF  (hidden comment: *)
Capacitor, Ceramic (MLCC), 15nF, ±10%, 50V, X7R, ±10%, SMD 0402; Manufacturer: CCTC; Manufacturer Part Number: TCC0402X7R153K500AT
footprint CAP-0402 (0402 (1005M) Capacitor)
pins: 1, 2

## TCC0402X7R182K500AT
designator C?  Capacitance: 1.8nF  (hidden comment: *)
Capacitor, Ceramic (MLCC), 1.8nF, ±10%, 50V, X7R, ±10%, SMD 0402; Manufacturer: CCTC; Manufacturer Part Number: TCC0402X7R182K500AT
footprint CAP-0402 (0402 (1005M) Capacitor)
pins: 1, 2

## TCC0402X7R221K500AT
designator C?  Capacitance: 220pF  (hidden comment: *)
Capacitor, Ceramic (MLCC), 220pF, ±10%, 50V, X7R, ±10%, SMD 0402; Manufacturer: CCTC; Manufacturer Part Number: TCC0402X7R221K500AT
footprint CAP-0402 (0402 (1005M) Capacitor)
pins: 1, 2

## TCC0402X7R223K160AT
designator C?  Capacitance: 22nF  (hidden comment: *)
Capacitor, Ceramic (MLCC), 22nF, ±10%, 16V, X7R, ±10%, SMD 0402; Manufacturer: CCTC; Manufacturer Part Number: TCC0402X7R223K160AT
footprint CAP-0402 (0402 (1005M) Capacitor)
pins: 1, 2

## TCC0402X7R223K250AT
designator C?  Capacitance: 22nF  (hidden comment: *)
Capacitor, Ceramic (MLCC), 22nF, ±10%, 25V, X7R, ±10%, SMD 0402; Manufacturer: CCTC; Manufacturer Part Number: TCC0402X7R223K250AT
footprint CAP-0402 (0402 (1005M) Capacitor)
pins: 1, 2

## TCC0402X7R223K500AT
designator C?  Capacitance: 22nF  (hidden comment: *)
Capacitor, Ceramic (MLCC), 22nF, ±10%, 50V, X7R, ±10%, SMD 0402; Manufacturer: CCTC; Manufacturer Part Number: TCC0402X7R223K500AT
footprint CAP-0402 (0402 (1005M) Capacitor)
pins: 1, 2

## TCC0402X7R224K160AT
designator C?  Capacitance: 220nF  (hidden comment: *)
Capacitor, Ceramic (MLCC), 220nF, ±10%, 16V, X7R, ±10%, SMD 0402; Manufacturer: CCTC; Manufacturer Part Number: TCC0402X7R224K160AT
footprint CAP-0402 (0402 (1005M) Capacitor)
pins: 1, 2

## TCC0402X7R331K500AT
designator C?  Capacitance: 330pF  (hidden comment: *)
Capacitor, Ceramic (MLCC), 330pF, ±10%, 50V, X7R, ±10%, SMD 0402; Manufacturer: CCTC; Manufacturer Part Number: TCC0402X7R331K500AT
footprint CAP-0402 (0402 (1005M) Capacitor)
pins: 1, 2

## TCC0402X7R332K500AT
designator C?  Capacitance: 3.3nF  (hidden comment: *)
Capacitor, Ceramic (MLCC), 3.3nF, ±10%, 50V, X7R, ±10%, SMD 0402; Manufacturer: CCTC; Manufacturer Part Number: TCC0402X7R332K500AT
footprint CAP-0402 (0402 (1005M) Capacitor)
pins: 1, 2

## TCC0402X7R333K250AT
designator C?  Capacitance: 33nF  (hidden comment: *)
Capacitor, Ceramic (MLCC), 33nF, ±10%, 25V, X7R, ±10%, SMD 0402; Manufacturer: CCTC; Manufacturer Part Number: TCC0402X7R333K250AT
footprint CAP-0402 (0402 (1005M) Capacitor)
pins: 1, 2

## TCC0402X7R391K500AT
designator C?  Capacitance: 390pF  (hidden comment: *)
Capacitor, Ceramic (MLCC), 390pF, ±10%, 50V, X7R, ±10%, SMD 0402; Manufacturer: CCTC; Manufacturer Part Number: TCC0402X7R391K500AT
footprint CAP-0402 (0402 (1005M) Capacitor)
pins: 1, 2

## TCC0402X7R393K500AT
designator C?  Capacitance: 39nF  (hidden comment: *)
Capacitor, Ceramic (MLCC), 39nF, ±10%, 50V, X7R, ±10%, SMD 0402; Manufacturer: CCTC; Manufacturer Part Number: TCC0402X7R393K500AT
footprint CAP-0402 (0402 (1005M) Capacitor)
pins: 1, 2

## TCC0402X7R471K500AT
designator C?  Capacitance: 470pF  (hidden comment: *)
Capacitor, Ceramic (MLCC), 470pF, ±10%, 50V, X7R, ±10%, SMD 0402; Manufacturer: CCTC; Manufacturer Part Number: TCC0402X7R471K500AT
footprint CAP-0402 (0402 (1005M) Capacitor)
pins: 1, 2

## TCC0402X7R472K500AT
designator C?  Capacitance: 4.7nF  (hidden comment: *)
Capacitor, Ceramic (MLCC), 4.7nF, ±10%, 50V, X7R, ±10%, SMD 0402; Manufacturer: CCTC; Manufacturer Part Number: TCC0402X7R472K500AT
footprint CAP-0402 (0402 (1005M) Capacitor)
pins: 1, 2

## TCC0402X7R473K160AT
designator C?  Capacitance: 47nF  (hidden comment: *)
Capacitor, Ceramic (MLCC), 47nF, ±10%, 16V, X7R, ±10%, SMD 0402; Manufacturer: CCTC; Manufacturer Part Number: TCC0402X7R473K160AT
footprint CAP-0402 (0402 (1005M) Capacitor)
pins: 1, 2

## TCC0402X7R473K250AT
designator C?  Capacitance: 47nF  (hidden comment: *)
Capacitor, Ceramic (MLCC), 47nF, ±10%, 25V, X7R, ±10%, SMD 0402; Manufacturer: CCTC; Manufacturer Part Number: TCC0402X7R473K250AT
footprint CAP-0402 (0402 (1005M) Capacitor)
pins: 1, 2

## TCC0402X7R473K500AT
designator C?  Capacitance: 47nF  (hidden comment: *)
Capacitor, Ceramic (MLCC), 47nF, ±10%, 50V, X7R, ±10%, SMD 0402; Manufacturer: CCTC; Manufacturer Part Number: TCC0402X7R473K500AT
footprint CAP-0402 (0402 (1005M) Capacitor)
pins: 1, 2

## TCC0402X7R563K160AT
designator C?  Capacitance: 56nF  (hidden comment: *)
Capacitor, Ceramic (MLCC), 56nF, ±10%, 16V, X7R, ±10%, SMD 0402; Manufacturer: CCTC; Manufacturer Part Number: TCC0402X7R563K160AT
footprint CAP-0402 (0402 (1005M) Capacitor)
pins: 1, 2

## TCC0402X7R681K500AT
designator C?  Capacitance: 680pF  (hidden comment: *)
Capacitor, Ceramic (MLCC), 680pF, ±10%, 50V, X7R, ±10%, SMD 0402; Manufacturer: CCTC; Manufacturer Part Number: TCC0402X7R681K500AT
footprint CAP-0402 (0402 (1005M) Capacitor)
pins: 1, 2

## TCC0402X7R683K160AT
designator C?  Capacitance: 68nF  (hidden comment: *)
Capacitor, Ceramic (MLCC), 68nF, ±10%, 16V, X7R, ±10%, SMD 0402; Manufacturer: CCTC; Manufacturer Part Number: TCC0402X7R683K160AT
footprint CAP-0402 (0402 (1005M) Capacitor)
pins: 1, 2

## TCC0402X7R823K160AT
designator C?  Capacitance: 82nF  (hidden comment: *)
Capacitor, Ceramic (MLCC), 82nF, ±10%, 16V, X7R, ±10%, SMD 0402; Manufacturer: CCTC; Manufacturer Part Number: TCC0402X7R823K160AT
footprint CAP-0402 (0402 (1005M) Capacitor)
pins: 1, 2

## TMK105B7103KVHF
designator C?  Capacitance: 10nF  (hidden comment: *)
Capacitor, Ceramic (MLCC), 10nF, ±10%, 25V, X7R, ±10%, SMD 0402; Manufacturer: Taiyo Yuden; Manufacturer Part Number: TMK105B7103KVHF
footprint CAP-0402 (0402 (1005M) Capacitor)
pins: 1, 2

## TMK105B7104KVHF
designator C?  Capacitance: 100nF  (hidden comment: *)
Capacitor, Ceramic (MLCC), 100nF, ±10%, 25V, X7R, ±10%, SMD 0402; Manufacturer: Taiyo Yuden; Manufacturer Part Number: TMK105B7104KVHF
footprint CAP-0402 (0402 (1005M) Capacitor)
pins: 1, 2

## TMK105B7223KV-F
designator C?  Capacitance: 22nF  (hidden comment: *)
Capacitor, Ceramic (MLCC), 22nF, ±10%, 25V, X7R, ±10%, SMD 0402; Manufacturer: Taiyo Yuden; Manufacturer Part Number: TMK105B7223KV-F
footprint CAP-0402 (0402 (1005M) Capacitor)
pins: 1, 2

## TMK105BJ105KV-F
designator C?  Capacitance: 1uF  (hidden comment: *)
Capacitor, Ceramic (MLCC), 1uF, ±10%, 25V, X5R, ±10%, SMD 0402; Manufacturer: Taiyo Yuden; Manufacturer Part Number: TMK105BJ105KV-F
footprint CAP-0402 (0402 (1005M) Capacitor)
pins: 1, 2

## TMK105SD122JV-F
designator C?  Capacitance: 1.2nF  (hidden comment: *)
Capacitor, Ceramic (MLCC), 1.2nF, ±5%, 25V, ±5%, SMD 0402; Manufacturer: Taiyo Yuden; Manufacturer Part Number: TMK105SD122JV-F
footprint CAP-0402 (0402 (1005M) Capacitor)
pins: 1, 2

## UMF105B7103KVHF
designator C?  Capacitance: 10nF  (hidden comment: *)
Capacitor, Ceramic (MLCC), 10nF, ±10%, 50V, X7R, ±10%, SMD 0402; Manufacturer: Taiyo Yuden; Manufacturer Part Number: UMF105B7103KVHF
footprint CAP-0402 (0402 (1005M) Capacitor)
pins: 1, 2

## UMK105ABJ474KV-F
designator C?  Capacitance: 470nF  (hidden comment: *)
Capacitor, Ceramic (MLCC), 470nF, ±10%, 50V, X5R, ±10%, SMD 0402; Manufacturer: Taiyo Yuden; Manufacturer Part Number: UMK105ABJ474KV-F
footprint CAP-0402 (0402 (1005M) Capacitor)
pins: 1, 2

## UMK105B7102KVHF
designator C?  Capacitance: 1nF  (hidden comment: *)
Capacitor, Ceramic (MLCC), 1nF, ±10%, 50V, X7R, ±10%, SMD 0402; Manufacturer: Taiyo Yuden; Manufacturer Part Number: UMK105B7102KVHF
footprint CAP-0402 (0402 (1005M) Capacitor)
pins: 1, 2

## UMK105B7103KVHF
designator C?  Capacitance: 10nF  (hidden comment: *)
Capacitor, Ceramic (MLCC), 10nF, ±10%, 50V, X7R, ±10%, SMD 0402; Manufacturer: Taiyo Yuden; Manufacturer Part Number: UMK105B7103KVHF
footprint CAP-0402 (0402 (1005M) Capacitor)
pins: 1, 2

## UMK105B7104KV-FR
designator C?  Capacitance: 100nF  (hidden comment: *)
Capacitor, Ceramic (MLCC), 100nF, ±10%, 50V, ±10%, SMD 0402; Manufacturer: Taiyo Yuden; Manufacturer Part Number: UMK105B7104KV-FR
footprint CAP-0402 (0402 (1005M) Capacitor)
pins: 1, 2

## UMK105B7104KVHF
designator C?  Capacitance: 100nF  (hidden comment: *)
Capacitor, Ceramic (MLCC), 100nF, ±10%, 50V, X7R, ±10%, SMD 0402; Manufacturer: Taiyo Yuden; Manufacturer Part Number: UMK105B7104KVHF
footprint CAP-0402 (0402 (1005M) Capacitor)
pins: 1, 2

## UMK105B7152KVHF
designator C?  Capacitance: 1.5nF  (hidden comment: *)
Capacitor, Ceramic (MLCC), 1.5nF, ±10%, 50V, X7R, ±10%, SMD 0402; Manufacturer: Taiyo Yuden; Manufacturer Part Number: UMK105B7152KVHF
footprint CAP-0402 (0402 (1005M) Capacitor)
pins: 1, 2

## UMK105B7221KVHF
designator C?  Capacitance: 220pF  (hidden comment: *)
Capacitor, Ceramic (MLCC), 220pF, ±10%, 50V, X7R, ±10%, SMD 0402; Manufacturer: Taiyo Yuden; Manufacturer Part Number: UMK105B7221KVHF
footprint CAP-0402 (0402 (1005M) Capacitor)
pins: 1, 2

## UMK105B7222KVHF
designator C?  Capacitance: 2.2nF  (hidden comment: *)
Capacitor, Ceramic (MLCC), 2.2nF, ±10%, 50V, X7R, ±10%, SMD 0402; Manufacturer: Taiyo Yuden; Manufacturer Part Number: UMK105B7222KVHF
footprint CAP-0402 (0402 (1005M) Capacitor)
pins: 1, 2

## UMK105B7223KVHF
designator C?  Capacitance: 22nF  (hidden comment: *)
Capacitor, Ceramic (MLCC), 22nF, ±10%, 50V, X7R, ±10%, SMD 0402; Manufacturer: Taiyo Yuden; Manufacturer Part Number: UMK105B7223KVHF
footprint CAP-0402 (0402 (1005M) Capacitor)
pins: 1, 2

## UMK105B7332KVHF
designator C?  Capacitance: 3.3nF  (hidden comment: *)
Capacitor, Ceramic (MLCC), 3.3nF, ±10%, 50V, X7R, ±10%, SMD 0402; Manufacturer: Taiyo Yuden; Manufacturer Part Number: UMK105B7332KVHF
footprint CAP-0402 (0402 (1005M) Capacitor)
pins: 1, 2

## UMK105B7471KV-F
designator C?  Capacitance: 470pF  (hidden comment: *)
Capacitor, Ceramic (MLCC), 470pF, ±10%, 50V, X7R, ±10%, SMD 0402; Manufacturer: Taiyo Yuden; Manufacturer Part Number: UMK105B7471KV-F
footprint CAP-0402 (0402 (1005M) Capacitor)
pins: 1, 2

## UMK105B7471KVHF
designator C?  Capacitance: 470pF  (hidden comment: *)
Capacitor, Ceramic (MLCC), 470pF, ±10%, 50V, X7R, ±10%, SMD 0402; Manufacturer: Taiyo Yuden; Manufacturer Part Number: UMK105B7471KVHF
footprint CAP-0402 (0402 (1005M) Capacitor)
pins: 1, 2

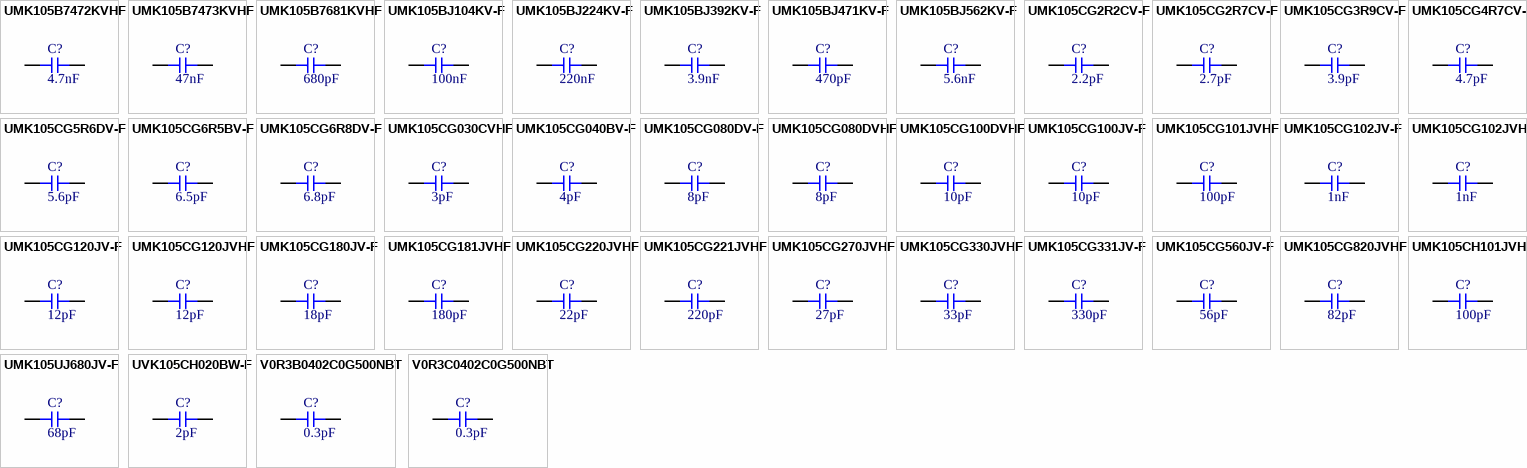
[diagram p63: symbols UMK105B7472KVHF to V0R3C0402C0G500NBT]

## UMK105B7472KVHF
designator C?  Capacitance: 4.7nF  (hidden comment: *)
Capacitor, Ceramic (MLCC), 4.7nF, ±10%, 50V, X7R, ±10%, SMD 0402; Manufacturer: Taiyo Yuden; Manufacturer Part Number: UMK105B7472KVHF
footprint CAP-0402 (0402 (1005M) Capacitor)
pins: 1, 2

## UMK105B7473KVHF
designator C?  Capacitance: 47nF  (hidden comment: *)
Capacitor, Ceramic (MLCC), 47nF, ±10%, 50V, X7R, ±10%, SMD 0402; Manufacturer: Taiyo Yuden; Manufacturer Part Number: UMK105B7473KVHF
footprint CAP-0402 (0402 (1005M) Capacitor)
pins: 1, 2

## UMK105B7681KVHF
designator C?  Capacitance: 680pF  (hidden comment: *)
Capacitor, Ceramic (MLCC), 680pF, ±10%, 50V, X7R, ±10%, SMD 0402; Manufacturer: Taiyo Yuden; Manufacturer Part Number: UMK105B7681KVHF
footprint CAP-0402 (0402 (1005M) Capacitor)
pins: 1, 2

## UMK105BJ104KV-F
designator C?  Capacitance: 100nF  (hidden comment: *)
Capacitor, Ceramic (MLCC), 100nF, ±10%, 50V, X5R, ±10%, SMD 0402; Manufacturer: Taiyo Yuden; Manufacturer Part Number: UMK105BJ104KV-F
footprint CAP-0402 (0402 (1005M) Capacitor)
pins: 1, 2

## UMK105BJ224KV-F
designator C?  Capacitance: 220nF  (hidden comment: *)
Capacitor, Ceramic (MLCC), 220nF, ±10%, 50V, ±10%, SMD 0402; Manufacturer: Taiyo Yuden; Manufacturer Part Number: UMK105BJ224KV-F
footprint CAP-0402 (0402 (1005M) Capacitor)
pins: 1, 2

## UMK105BJ392KV-F
designator C?  Capacitance: 3.9nF  (hidden comment: *)
Capacitor, Ceramic (MLCC), 3.9nF, ±10%, 50V, X5R, ±10%, SMD 0402; Manufacturer: Taiyo Yuden; Manufacturer Part Number: UMK105BJ392KV-F
footprint CAP-0402 (0402 (1005M) Capacitor)
pins: 1, 2

## UMK105BJ471KV-F
designator C?  Capacitance: 470pF  (hidden comment: *)
Capacitor, Ceramic (MLCC), 470pF, ±10%, 50V, X5R, ±10%, SMD 0402; Manufacturer: Taiyo Yuden; Manufacturer Part Number: UMK105BJ471KV-F
footprint CAP-0402 (0402 (1005M) Capacitor)
pins: 1, 2

## UMK105BJ562KV-F
designator C?  Capacitance: 5.6nF  (hidden comment: *)
Capacitor, Ceramic (MLCC), 5.6nF, ±10%, 50V, X5R, ±10%, SMD 0402; Manufacturer: Taiyo Yuden; Manufacturer Part Number: UMK105BJ562KV-F
footprint CAP-0402 (0402 (1005M) Capacitor)
pins: 1, 2

## UMK105CG2R2CV-F
designator C?  Capacitance: 2.2pF  (hidden comment: *)
Capacitor, Ceramic (MLCC), 2.2pF, ±0.25pF, 50V, C0G, ±0.25pF, SMD 0402; Manufacturer: Taiyo Yuden; Manufacturer Part Number: UMK105CG2R2CV-F
footprint CAP-0402 (0402 (1005M) Capacitor)
pins: 1, 2

## UMK105CG2R7CV-F
designator C?  Capacitance: 2.7pF  (hidden comment: *)
Capacitor, Ceramic (MLCC), 2.7pF, ±0.25pF, 50V, C0G, ±0.25pF, SMD 0402; Manufacturer: Taiyo Yuden; Manufacturer Part Number: UMK105CG2R7CV-F
footprint CAP-0402 (0402 (1005M) Capacitor)
pins: 1, 2

## UMK105CG3R9CV-F
designator C?  Capacitance: 3.9pF  (hidden comment: *)
Capacitor, Ceramic (MLCC), 3.9pF, ±0.25pF, 50V, C0G, ±0.25pF, SMD 0402; Manufacturer: Taiyo Yuden; Manufacturer Part Number: UMK105CG3R9CV-F
footprint CAP-0402 (0402 (1005M) Capacitor)
pins: 1, 2

## UMK105CG4R7CV-F
designator C?  Capacitance: 4.7pF  (hidden comment: *)
Capacitor, Ceramic (MLCC), 4.7pF, ±0.25pF, 50V, C0G, ±0.25pF, SMD 0402; Manufacturer: Taiyo Yuden; Manufacturer Part Number: UMK105CG4R7CV-F
footprint CAP-0402 (0402 (1005M) Capacitor)
pins: 1, 2

## UMK105CG5R6DV-F
designator C?  Capacitance: 5.6pF  (hidden comment: *)
Capacitor, Ceramic (MLCC), 5.6pF, ±0.5pF, 50V, C0G, ±0.5pF, SMD 0402; Manufacturer: Taiyo Yuden; Manufacturer Part Number: UMK105CG5R6DV-F
footprint CAP-0402 (0402 (1005M) Capacitor)
pins: 1, 2

## UMK105CG6R5BV-F
designator C?  Capacitance: 6.5pF  (hidden comment: *)
Capacitor, Ceramic (MLCC), 6.5pF, ±0.1pF, 50V, C0G, ±0.1pF, SMD 0402; Manufacturer: Taiyo Yuden; Manufacturer Part Number: UMK105CG6R5BV-F
footprint CAP-0402 (0402 (1005M) Capacitor)
pins: 1, 2

## UMK105CG6R8DV-F
designator C?  Capacitance: 6.8pF  (hidden comment: *)
Capacitor, Ceramic (MLCC), 6.8pF, ±0.5pF, 50V, C0G, ±0.5pF, SMD 0402; Manufacturer: Taiyo Yuden; Manufacturer Part Number: UMK105CG6R8DV-F
footprint CAP-0402 (0402 (1005M) Capacitor)
pins: 1, 2

## UMK105CG030CVHF
designator C?  Capacitance: 3pF  (hidden comment: *)
Capacitor, Ceramic (MLCC), 3pF, ±0.25pF, 50V, C0G, ±0.25pF, SMD 0402; Manufacturer: Taiyo Yuden; Manufacturer Part Number: UMK105CG030CVHF
footprint CAP-0402 (0402 (1005M) Capacitor)
pins: 1, 2

## UMK105CG040BV-F
designator C?  Capacitance: 4pF  (hidden comment: *)
Capacitor, Ceramic (MLCC), 4pF, ±0.1pF, 50V, C0G, ±0.1pF, SMD 0402; Manufacturer: Taiyo Yuden; Manufacturer Part Number: UMK105CG040BV-F
footprint CAP-0402 (0402 (1005M) Capacitor)
pins: 1, 2

## UMK105CG080DV-F
designator C?  Capacitance: 8pF  (hidden comment: *)
Capacitor, Ceramic (MLCC), 8pF, ±0.5pF, 50V, C0G, ±0.5pF, SMD 0402; Manufacturer: Taiyo Yuden; Manufacturer Part Number: UMK105CG080DV-F
footprint CAP-0402 (0402 (1005M) Capacitor)
pins: 1, 2

## UMK105CG080DVHF
designator C?  Capacitance: 8pF  (hidden comment: *)
Capacitor, Ceramic (MLCC), 8pF, ±0.5pF, 50V, C0G, ±0.5pF, SMD 0402; Manufacturer: Taiyo Yuden; Manufacturer Part Number: UMK105CG080DVHF
footprint CAP-0402 (0402 (1005M) Capacitor)
pins: 1, 2

## UMK105CG100DVHF
designator C?  Capacitance: 10pF  (hidden comment: *)
Capacitor, Ceramic (MLCC), 10pF, ±0.5pF, 50V, C0G, ±0.5pF, SMD 0402; Manufacturer: Taiyo Yuden; Manufacturer Part Number: UMK105CG100DVHF
footprint CAP-0402 (0402 (1005M) Capacitor)
pins: 1, 2

## UMK105CG100JV-F
designator C?  Capacitance: 10pF  (hidden comment: *)
Capacitor, Ceramic (MLCC), 10pF, ±5%, 50V, C0G, ±5%, SMD 0402; Manufacturer: Taiyo Yuden; Manufacturer Part Number: UMK105CG100JV-F
footprint CAP-0402 (0402 (1005M) Capacitor)
pins: 1, 2

## UMK105CG101JVHF
designator C?  Capacitance: 100pF  (hidden comment: *)
Capacitor, Ceramic (MLCC), 100pF, ±5%, 50V, C0G, ±5%, SMD 0402; Manufacturer: Taiyo Yuden; Manufacturer Part Number: UMK105CG101JVHF
footprint CAP-0402 (0402 (1005M) Capacitor)
pins: 1, 2

## UMK105CG102JV-F
designator C?  Capacitance: 1nF  (hidden comment: *)
Capacitor, Ceramic (MLCC), 1nF, ±5%, 50V, C0G, ±5%, SMD 0402; Manufacturer: Taiyo Yuden; Manufacturer Part Number: UMK105CG102JV-F
footprint CAP-0402 (0402 (1005M) Capacitor)
pins: 1, 2

## UMK105CG102JVHF
designator C?  Capacitance: 1nF  (hidden comment: *)
Capacitor, Ceramic (MLCC), 1nF, ±5%, 50V, C0G, ±5%, SMD 0402; Manufacturer: Taiyo Yuden; Manufacturer Part Number: UMK105CG102JVHF
footprint CAP-0402 (0402 (1005M) Capacitor)
pins: 1, 2

## UMK105CG120JV-F
designator C?  Capacitance: 12pF  (hidden comment: *)
Capacitor, Ceramic (MLCC), 12pF, ±5%, 50V, C0G, ±5%, SMD 0402; Manufacturer: Taiyo Yuden; Manufacturer Part Number: UMK105CG120JV-F
footprint CAP-0402 (0402 (1005M) Capacitor)
pins: 1, 2

## UMK105CG120JVHF
designator C?  Capacitance: 12pF  (hidden comment: *)
Capacitor, Ceramic (MLCC), 12pF, ±5%, 50V, C0G, ±5%, SMD 0402; Manufacturer: Taiyo Yuden; Manufacturer Part Number: UMK105CG120JVHF
footprint CAP-0402 (0402 (1005M) Capacitor)
pins: 1, 2

## UMK105CG180JV-F
designator C?  Capacitance: 18pF  (hidden comment: *)
Capacitor, Ceramic (MLCC), 18pF, ±5%, 50V, C0G, ±5%, SMD 0402; Manufacturer: Taiyo Yuden; Manufacturer Part Number: UMK105CG180JV-F
footprint CAP-0402 (0402 (1005M) Capacitor)
pins: 1, 2

## UMK105CG181JVHF
designator C?  Capacitance: 180pF  (hidden comment: *)
Capacitor, Ceramic (MLCC), 180pF, ±5%, 50V, C0G, ±5%, SMD 0402; Manufacturer: Taiyo Yuden; Manufacturer Part Number: UMK105CG181JVHF
footprint CAP-0402 (0402 (1005M) Capacitor)
pins: 1, 2

## UMK105CG220JVHF
designator C?  Capacitance: 22pF  (hidden comment: *)
Capacitor, Ceramic (MLCC), 22pF, ±5%, 50V, C0G, ±5%, SMD 0402; Manufacturer: Taiyo Yuden; Manufacturer Part Number: UMK105CG220JVHF
footprint CAP-0402 (0402 (1005M) Capacitor)
pins: 1, 2

## UMK105CG221JVHF
designator C?  Capacitance: 220pF  (hidden comment: *)
Capacitor, Ceramic (MLCC), 220pF, ±5%, 50V, C0G, ±5%, SMD 0402; Manufacturer: Taiyo Yuden; Manufacturer Part Number: UMK105CG221JVHF
footprint CAP-0402 (0402 (1005M) Capacitor)
pins: 1, 2

## UMK105CG270JVHF
designator C?  Capacitance: 27pF  (hidden comment: *)
Capacitor, Ceramic (MLCC), 27pF, ±5%, 50V, C0G, ±5%, SMD 0402; Manufacturer: Taiyo Yuden; Manufacturer Part Number: UMK105CG270JVHF
footprint CAP-0402 (0402 (1005M) Capacitor)
pins: 1, 2

## UMK105CG330JVHF
designator C?  Capacitance: 33pF  (hidden comment: *)
Capacitor, Ceramic (MLCC), 33pF, ±5%, 50V, C0G, ±5%, SMD 0402; Manufacturer: Taiyo Yuden; Manufacturer Part Number: UMK105CG330JVHF
footprint CAP-0402 (0402 (1005M) Capacitor)
pins: 1, 2

## UMK105CG331JV-F
designator C?  Capacitance: 330pF  (hidden comment: *)
Capacitor, Ceramic (MLCC), 330pF, ±5%, 50V, C0G, ±5%, SMD 0402; Manufacturer: Taiyo Yuden; Manufacturer Part Number: UMK105CG331JV-F
footprint CAP-0402 (0402 (1005M) Capacitor)
pins: 1, 2

## UMK105CG560JV-F
designator C?  Capacitance: 56pF  (hidden comment: *)
Capacitor, Ceramic (MLCC), 56pF, ±5%, 50V, C0G, ±5%, SMD 0402; Manufacturer: Taiyo Yuden; Manufacturer Part Number: UMK105CG560JV-F
footprint CAP-0402 (0402 (1005M) Capacitor)
pins: 1, 2

## UMK105CG820JVHF
designator C?  Capacitance: 82pF  (hidden comment: *)
Capacitor, Ceramic (MLCC), 82pF, ±5%, 50V, C0G, ±5%, SMD 0402; Manufacturer: Taiyo Yuden; Manufacturer Part Number: UMK105CG820JVHF
footprint CAP-0402 (0402 (1005M) Capacitor)
pins: 1, 2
